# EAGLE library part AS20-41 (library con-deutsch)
DEUTSCH Connector
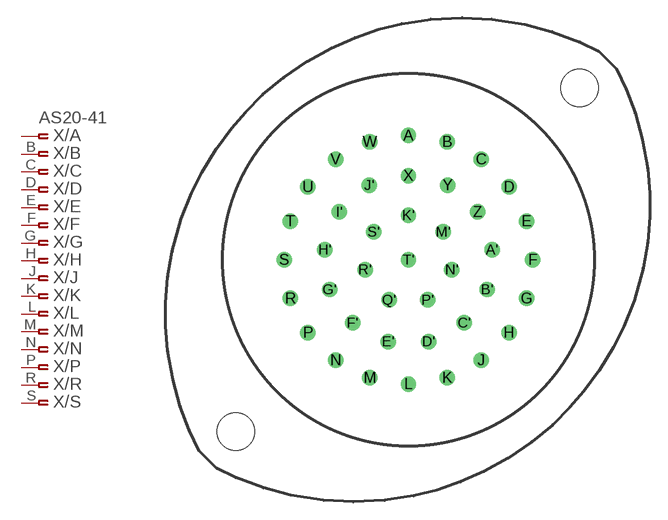
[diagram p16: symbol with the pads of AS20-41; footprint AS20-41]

Designator prefix X; gates /A=PINF_VAL /B=ASPINF /C=ASPINF /D=ASPINF /E=ASPINF /F=ASPINF /G=ASPINF /H=ASPINF /J=ASPINF /K=ASPINF /L=ASPINF /M=ASPINF /N=ASPINF /P=ASPINF /R=ASPINF /S=ASPINF /T=ASPINF /U=ASPINF /V=ASPINF /W=ASPINF /X=ASPINF /Y=ASPINF /Z=ASPINF /A'=PINF_VAL /B'=ASPINF /C'=ASPINF /D'=ASPINF /E'=ASPINF /F'=ASPINF /G'=ASPINF /H'=ASPINF /J'=ASPINF /K'=ASPINF /Q'=ASPINF /M'=ASPINF /N'=ASPINF /P'=ASPINF /R'=ASPINF /S'=ASPINF /T'=ASPINF /I'=ASPINF

## AS20-41 (OC_FARNELL: unknown; OC_NEWARK: unknown)  [AS20-41]
A  /A:1  pas
A'  /A':1  pas
B  /B:1  pas
B'  /B':1  pas
C  /C:1  pas
C'  /C':1  pas
D  /D:1  pas
D'  /D':1  pas
E  /E:1  pas
E'  /E':1  pas
F  /F:1  pas
F'  /F':1  pas
G  /G:1  pas
G'  /G':1  pas
H  /H:1  pas
H'  /H':1  pas
I'  /I':1  pas
J  /J:1  pas
J'  /J':1  pas
K  /K:1  pas
K'  /K':1  pas
L  /L:1  pas
M  /M:1  pas
M'  /M':1  pas
N  /N:1  pas
N'  /N':1  pas
P  /P:1  pas
P'  /P':1  pas
Q'  /Q':1  pas
R  /R:1  pas
R'  /R':1  pas
S  /S:1  pas
S'  /S':1  pas
T  /T:1  pas
T'  /T':1  pas
U  /U:1  pas
V  /V:1  pas
W  /W:1  pas
X  /X:1  pas
Y  /Y:1  pas
Z  /Z:1  pas

## Footprint AS20-41 (pad centres in mm)
DEUTSCH Connector
drill 0.813 round: A 0,10.617; A' 7.137,0.864; B 3.302,10.084; B' 6.731,-2.54; C 6.223,8.585; C' 4.775,-5.385; D 8.585,6.223; D' 1.727,-6.985; E 10.084,3.302; E' -1.727,-6.985; F 10.617,0; F' -4.775,-5.385; G 10.084,-3.302; G' -6.731,-2.54; H 8.585,-6.223; H' -7.137,0.864; I' -5.918,4.089; J 6.223,-8.585; J' -3.353,6.375; K 3.302,-10.084; K' 0,3.81; L 0,-10.617; M -3.302,-10.084; M' 2.972,2.388; N -6.223,-8.585; N' 3.708,-0.838; P -8.585,-6.223; P' 1.651,-3.429; Q' -1.651,-3.429; R -10.084,-3.302; R' -3.708,-0.838; S -10.617,0; S' -2.972,2.388; T -10.084,3.302; T' 0,0; U -8.585,6.223; V -6.223,8.585; W -3.302,10.084; X 0,7.188; Y 3.353,6.375; Z 5.918,4.089
hole 3.2 at -14.764,-14.7
hole 3.2 at 14.636,14.7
